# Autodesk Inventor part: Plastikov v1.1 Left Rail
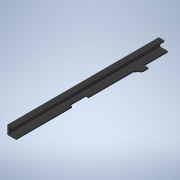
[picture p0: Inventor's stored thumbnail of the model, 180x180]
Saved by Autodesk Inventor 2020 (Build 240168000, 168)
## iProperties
Created: 2020-05
Part Number: Plastikov v1.1 Left Rail
Material: Generic
Document SubType Name: Modeling
Designer: Iv. Tr.
Density: 1 g/cm^3
Appearance: Default
Title: D:\Downloads\Plastikov-v1-3\STEP\Plastikov v1.1 Left Rail.stp
Author: johne
Sending System: Autodesk Inventor 2020
Preprocessor: ST-DEVELOPER v18
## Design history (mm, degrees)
feature "Solid1"
body "Solid2"
